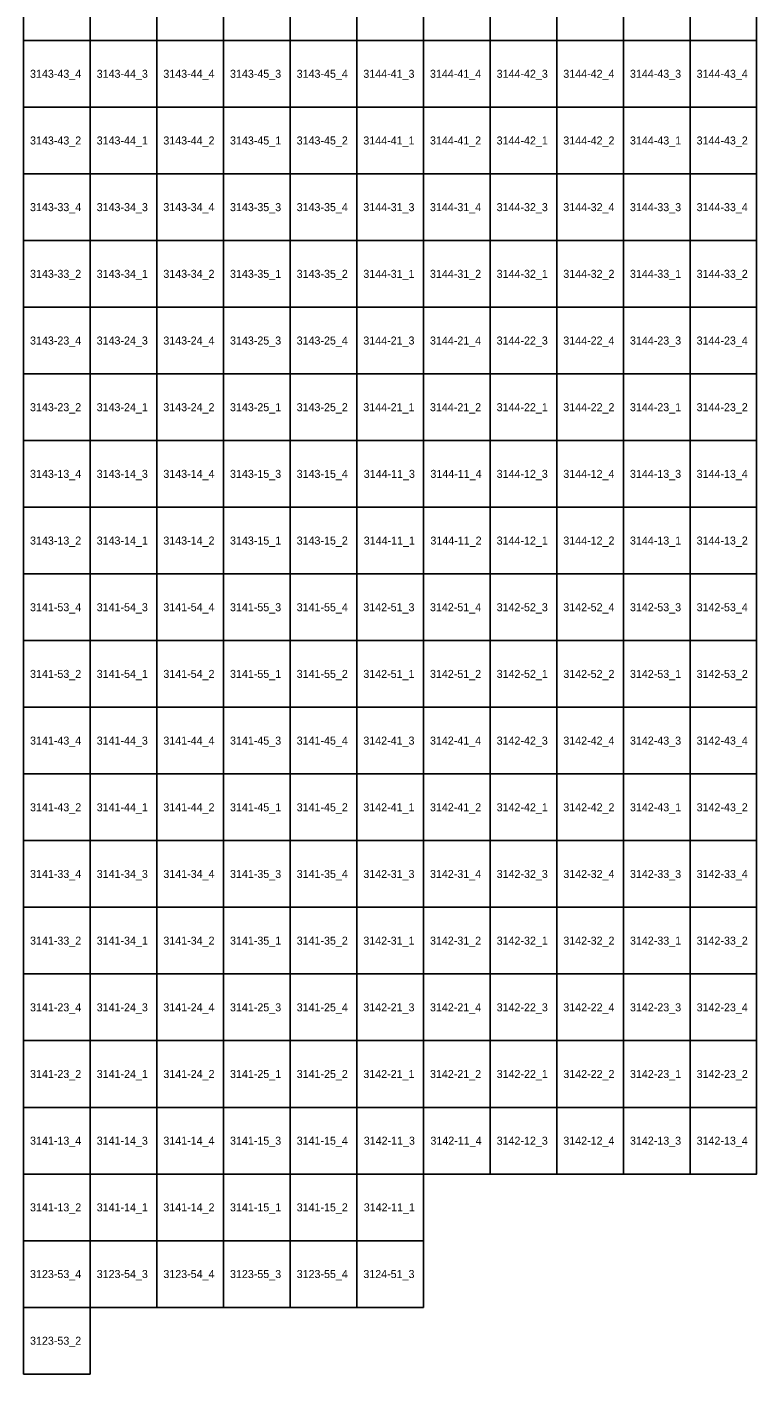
# Model space of a CAD drawing. Extents: x 312500 to 765000, y 172500 to 440000.
# Drawn here: x 362632 to 389827, y 245000 to 295507 of the extents above; entities that cross this region are included whole.
import ezdxf

# ---------------------------------------------------------------- set-up
doc = ezdxf.new("R2010")
doc.units = 0
doc.layers.add('Topo5_ramis_TKS2025', color=7, linetype='Continuous')
doc.layers.add('Topo5_ramis_TKS2025_Nr', color=7, linetype='Continuous')

msp = doc.modelspace()

# ---------------------------------------------------------------- linework, layer by layer
at = {"layer": 'Topo5_ramis_TKS2025'}
for points in [[(362500, 295000), (362500, 297500), (365000, 297500), (365000, 295000), (362500, 295000)], [(365000, 295000), (365000, 297500), (367500, 297500), (367500, 295000), (365000, 295000)], [(367500, 295000), (367500, 297500), (370000, 297500), (370000, 295000), (367500, 295000)], [(370000, 295000), (370000, 297500), (372500, 297500), (372500, 295000), (370000, 295000)], [(372500, 295000), (372500, 297500), (375000, 297500), (375000, 295000), (372500, 295000)], [(375000, 295000), (375000, 297500), (377500, 297500), (377500, 295000), (375000, 295000)], [(377500, 295000), (377500, 297500), (380000, 297500), (380000, 295000), (377500, 295000)], [(380000, 295000), (380000, 297500), (382500, 297500), (382500, 295000), (380000, 295000)], [(382500, 295000), (382500, 297500), (385000, 297500), (385000, 295000), (382500, 295000)], [(385000, 295000), (385000, 297500), (387500, 297500), (387500, 295000), (385000, 295000)], [(387500, 295000), (387500, 297500), (390000, 297500), (390000, 295000), (387500, 295000)], [(362500, 292500), (362500, 295000), (365000, 295000), (365000, 292500), (362500, 292500)], [(365000, 292500), (365000, 295000), (367500, 295000), (367500, 292500), (365000, 292500)], [(367500, 292500), (367500, 295000), (370000, 295000), (370000, 292500), (367500, 292500)], [(370000, 292500), (370000, 295000), (372500, 295000), (372500, 292500), (370000, 292500)], [(372500, 292500), (372500, 295000), (375000, 295000), (375000, 292500), (372500, 292500)], [(375000, 292500), (375000, 295000), (377500, 295000), (377500, 292500), (375000, 292500)], [(377500, 292500), (377500, 295000), (380000, 295000), (380000, 292500), (377500, 292500)], [(380000, 292500), (380000, 295000), (382500, 295000), (382500, 292500), (380000, 292500)], [(382500, 292500), (382500, 295000), (385000, 295000), (385000, 292500), (382500, 292500)], [(385000, 292500), (385000, 295000), (387500, 295000), (387500, 292500), (385000, 292500)], [(387500, 292500), (387500, 295000), (390000, 295000), (390000, 292500), (387500, 292500)], [(362500, 290000), (362500, 292500), (365000, 292500), (365000, 290000), (362500, 290000)], [(365000, 290000), (365000, 292500), (367500, 292500), (367500, 290000), (365000, 290000)], [(367500, 290000), (367500, 292500), (370000, 292500), (370000, 290000), (367500, 290000)], [(370000, 290000), (370000, 292500), (372500, 292500), (372500, 290000), (370000, 290000)], [(372500, 290000), (372500, 292500), (375000, 292500), (375000, 290000), (372500, 290000)], [(375000, 290000), (375000, 292500), (377500, 292500), (377500, 290000), (375000, 290000)], [(377500, 290000), (377500, 292500), (380000, 292500), (380000, 290000), (377500, 290000)], [(380000, 290000), (380000, 292500), (382500, 292500), (382500, 290000), (380000, 290000)], [(382500, 290000), (382500, 292500), (385000, 292500), (385000, 290000), (382500, 290000)], [(385000, 290000), (385000, 292500), (387500, 292500), (387500, 290000), (385000, 290000)], [(387500, 290000), (387500, 292500), (390000, 292500), (390000, 290000), (387500, 290000)], [(362500, 287500), (362500, 290000), (365000, 290000), (365000, 287500), (362500, 287500)], [(365000, 287500), (365000, 290000), (367500, 290000), (367500, 287500), (365000, 287500)], [(367500, 287500), (367500, 290000), (370000, 290000), (370000, 287500), (367500, 287500)], [(370000, 287500), (370000, 290000), (372500, 290000), (372500, 287500), (370000, 287500)], [(372500, 287500), (372500, 290000), (375000, 290000), (375000, 287500), (372500, 287500)], [(375000, 287500), (375000, 290000), (377500, 290000), (377500, 287500), (375000, 287500)], [(377500, 287500), (377500, 290000), (380000, 290000), (380000, 287500), (377500, 287500)], [(380000, 287500), (380000, 290000), (382500, 290000), (382500, 287500), (380000, 287500)], [(382500, 287500), (382500, 290000), (385000, 290000), (385000, 287500), (382500, 287500)], [(385000, 287500), (385000, 290000), (387500, 290000), (387500, 287500), (385000, 287500)], [(387500, 287500), (387500, 290000), (390000, 290000), (390000, 287500), (387500, 287500)], [(362500, 285000), (362500, 287500), (365000, 287500), (365000, 285000), (362500, 285000)], [(365000, 285000), (365000, 287500), (367500, 287500), (367500, 285000), (365000, 285000)], [(367500, 285000), (367500, 287500), (370000, 287500), (370000, 285000), (367500, 285000)], [(370000, 285000), (370000, 287500), (372500, 287500), (372500, 285000), (370000, 285000)], [(372500, 285000), (372500, 287500), (375000, 287500), (375000, 285000), (372500, 285000)], [(375000, 285000), (375000, 287500), (377500, 287500), (377500, 285000), (375000, 285000)], [(377500, 285000), (377500, 287500), (380000, 287500), (380000, 285000), (377500, 285000)], [(380000, 285000), (380000, 287500), (382500, 287500), (382500, 285000), (380000, 285000)], [(382500, 285000), (382500, 287500), (385000, 287500), (385000, 285000), (382500, 285000)], [(385000, 285000), (385000, 287500), (387500, 287500), (387500, 285000), (385000, 285000)], [(387500, 285000), (387500, 287500), (390000, 287500), (390000, 285000), (387500, 285000)], [(362500, 282500), (362500, 285000), (365000, 285000), (365000, 282500), (362500, 282500)], [(365000, 282500), (365000, 285000), (367500, 285000), (367500, 282500), (365000, 282500)], [(367500, 282500), (367500, 285000), (370000, 285000), (370000, 282500), (367500, 282500)], [(370000, 282500), (370000, 285000), (372500, 285000), (372500, 282500), (370000, 282500)], [(372500, 282500), (372500, 285000), (375000, 285000), (375000, 282500), (372500, 282500)], [(375000, 282500), (375000, 285000), (377500, 285000), (377500, 282500), (375000, 282500)], [(377500, 282500), (377500, 285000), (380000, 285000), (380000, 282500), (377500, 282500)], [(380000, 282500), (380000, 285000), (382500, 285000), (382500, 282500), (380000, 282500)], [(382500, 282500), (382500, 285000), (385000, 285000), (385000, 282500), (382500, 282500)], [(385000, 282500), (385000, 285000), (387500, 285000), (387500, 282500), (385000, 282500)], [(387500, 282500), (387500, 285000), (390000, 285000), (390000, 282500), (387500, 282500)], [(362500, 280000), (362500, 282500), (365000, 282500), (365000, 280000), (362500, 280000)], [(365000, 280000), (365000, 282500), (367500, 282500), (367500, 280000), (365000, 280000)], [(367500, 280000), (367500, 282500), (370000, 282500), (370000, 280000), (367500, 280000)], [(370000, 280000), (370000, 282500), (372500, 282500), (372500, 280000), (370000, 280000)], [(372500, 280000), (372500, 282500), (375000, 282500), (375000, 280000), (372500, 280000)], [(375000, 280000), (375000, 282500), (377500, 282500), (377500, 280000), (375000, 280000)], [(377500, 280000), (377500, 282500), (380000, 282500), (380000, 280000), (377500, 280000)], [(380000, 280000), (380000, 282500), (382500, 282500), (382500, 280000), (380000, 280000)], [(382500, 280000), (382500, 282500), (385000, 282500), (385000, 280000), (382500, 280000)], [(385000, 280000), (385000, 282500), (387500, 282500), (387500, 280000), (385000, 280000)], [(387500, 280000), (387500, 282500), (390000, 282500), (390000, 280000), (387500, 280000)], [(362500, 277500), (362500, 280000), (365000, 280000), (365000, 277500), (362500, 277500)], [(365000, 277500), (365000, 280000), (367500, 280000), (367500, 277500), (365000, 277500)], [(367500, 277500), (367500, 280000), (370000, 280000), (370000, 277500), (367500, 277500)], [(370000, 277500), (370000, 280000), (372500, 280000), (372500, 277500), (370000, 277500)], [(372500, 277500), (372500, 280000), (375000, 280000), (375000, 277500), (372500, 277500)], [(375000, 277500), (375000, 280000), (377500, 280000), (377500, 277500), (375000, 277500)], [(377500, 277500), (377500, 280000), (380000, 280000), (380000, 277500), (377500, 277500)], [(380000, 277500), (380000, 280000), (382500, 280000), (382500, 277500), (380000, 277500)], [(382500, 277500), (382500, 280000), (385000, 280000), (385000, 277500), (382500, 277500)], [(385000, 277500), (385000, 280000), (387500, 280000), (387500, 277500), (385000, 277500)], [(387500, 277500), (387500, 280000), (390000, 280000), (390000, 277500), (387500, 277500)], [(362500, 275000), (362500, 277500), (365000, 277500), (365000, 275000), (362500, 275000)], [(365000, 275000), (365000, 277500), (367500, 277500), (367500, 275000), (365000, 275000)], [(367500, 275000), (367500, 277500), (370000, 277500), (370000, 275000), (367500, 275000)], [(370000, 275000), (370000, 277500), (372500, 277500), (372500, 275000), (370000, 275000)], [(372500, 275000), (372500, 277500), (375000, 277500), (375000, 275000), (372500, 275000)], [(375000, 275000), (375000, 277500), (377500, 277500), (377500, 275000), (375000, 275000)], [(377500, 275000), (377500, 277500), (380000, 277500), (380000, 275000), (377500, 275000)], [(380000, 275000), (380000, 277500), (382500, 277500), (382500, 275000), (380000, 275000)], [(382500, 275000), (382500, 277500), (385000, 277500), (385000, 275000), (382500, 275000)], [(385000, 275000), (385000, 277500), (387500, 277500), (387500, 275000), (385000, 275000)], [(387500, 275000), (387500, 277500), (390000, 277500), (390000, 275000), (387500, 275000)], [(362500, 272500), (362500, 275000), (365000, 275000), (365000, 272500), (362500, 272500)], [(365000, 272500), (365000, 275000), (367500, 275000), (367500, 272500), (365000, 272500)], [(367500, 272500), (367500, 275000), (370000, 275000), (370000, 272500), (367500, 272500)], [(370000, 272500), (370000, 275000), (372500, 275000), (372500, 272500), (370000, 272500)], [(372500, 272500), (372500, 275000), (375000, 275000), (375000, 272500), (372500, 272500)], [(375000, 272500), (375000, 275000), (377500, 275000), (377500, 272500), (375000, 272500)], [(377500, 272500), (377500, 275000), (380000, 275000), (380000, 272500), (377500, 272500)], [(380000, 272500), (380000, 275000), (382500, 275000), (382500, 272500), (380000, 272500)], [(382500, 272500), (382500, 275000), (385000, 275000), (385000, 272500), (382500, 272500)], [(385000, 272500), (385000, 275000), (387500, 275000), (387500, 272500), (385000, 272500)], [(387500, 272500), (387500, 275000), (390000, 275000), (390000, 272500), (387500, 272500)], [(362500, 270000), (362500, 272500), (365000, 272500), (365000, 270000), (362500, 270000)], [(365000, 270000), (365000, 272500), (367500, 272500), (367500, 270000), (365000, 270000)], [(367500, 270000), (367500, 272500), (370000, 272500), (370000, 270000), (367500, 270000)], [(370000, 270000), (370000, 272500), (372500, 272500), (372500, 270000), (370000, 270000)], [(372500, 270000), (372500, 272500), (375000, 272500), (375000, 270000), (372500, 270000)], [(375000, 270000), (375000, 272500), (377500, 272500), (377500, 270000), (375000, 270000)], [(377500, 270000), (377500, 272500), (380000, 272500), (380000, 270000), (377500, 270000)], [(380000, 270000), (380000, 272500), (382500, 272500), (382500, 270000), (380000, 270000)], [(382500, 270000), (382500, 272500), (385000, 272500), (385000, 270000), (382500, 270000)], [(385000, 270000), (385000, 272500), (387500, 272500), (387500, 270000), (385000, 270000)], [(387500, 270000), (387500, 272500), (390000, 272500), (390000, 270000), (387500, 270000)], [(362500, 267500), (362500, 270000), (365000, 270000), (365000, 267500), (362500, 267500)], [(365000, 267500), (365000, 270000), (367500, 270000), (367500, 267500), (365000, 267500)], [(367500, 267500), (367500, 270000), (370000, 270000), (370000, 267500), (367500, 267500)], [(370000, 267500), (370000, 270000), (372500, 270000), (372500, 267500), (370000, 267500)], [(372500, 267500), (372500, 270000), (375000, 270000), (375000, 267500), (372500, 267500)], [(375000, 267500), (375000, 270000), (377500, 270000), (377500, 267500), (375000, 267500)], [(377500, 267500), (377500, 270000), (380000, 270000), (380000, 267500), (377500, 267500)], [(380000, 267500), (380000, 270000), (382500, 270000), (382500, 267500), (380000, 267500)], [(382500, 267500), (382500, 270000), (385000, 270000), (385000, 267500), (382500, 267500)], [(385000, 267500), (385000, 270000), (387500, 270000), (387500, 267500), (385000, 267500)], [(387500, 267500), (387500, 270000), (390000, 270000), (390000, 267500), (387500, 267500)], [(362500, 265000), (362500, 267500), (365000, 267500), (365000, 265000), (362500, 265000)], [(365000, 265000), (365000, 267500), (367500, 267500), (367500, 265000), (365000, 265000)], [(367500, 265000), (367500, 267500), (370000, 267500), (370000, 265000), (367500, 265000)], [(370000, 265000), (370000, 267500), (372500, 267500), (372500, 265000), (370000, 265000)], [(372500, 265000), (372500, 267500), (375000, 267500), (375000, 265000), (372500, 265000)], [(375000, 265000), (375000, 267500), (377500, 267500), (377500, 265000), (375000, 265000)], [(377500, 265000), (377500, 267500), (380000, 267500), (380000, 265000), (377500, 265000)], [(380000, 265000), (380000, 267500), (382500, 267500), (382500, 265000), (380000, 265000)], [(382500, 265000), (382500, 267500), (385000, 267500), (385000, 265000), (382500, 265000)], [(385000, 265000), (385000, 267500), (387500, 267500), (387500, 265000), (385000, 265000)], [(387500, 265000), (387500, 267500), (390000, 267500), (390000, 265000), (387500, 265000)], [(362500, 262500), (362500, 265000), (365000, 265000), (365000, 262500), (362500, 262500)], [(365000, 262500), (365000, 265000), (367500, 265000), (367500, 262500), (365000, 262500)], [(367500, 262500), (367500, 265000), (370000, 265000), (370000, 262500), (367500, 262500)], [(370000, 262500), (370000, 265000), (372500, 265000), (372500, 262500), (370000, 262500)], [(372500, 262500), (372500, 265000), (375000, 265000), (375000, 262500), (372500, 262500)], [(375000, 262500), (375000, 265000), (377500, 265000), (377500, 262500), (375000, 262500)], [(377500, 262500), (377500, 265000), (380000, 265000), (380000, 262500), (377500, 262500)], [(380000, 262500), (380000, 265000), (382500, 265000), (382500, 262500), (380000, 262500)], [(382500, 262500), (382500, 265000), (385000, 265000), (385000, 262500), (382500, 262500)], [(385000, 262500), (385000, 265000), (387500, 265000), (387500, 262500), (385000, 262500)], [(387500, 262500), (387500, 265000), (390000, 265000), (390000, 262500), (387500, 262500)], [(362500, 260000), (362500, 262500), (365000, 262500), (365000, 260000), (362500, 260000)], [(365000, 260000), (365000, 262500), (367500, 262500), (367500, 260000), (365000, 260000)], [(367500, 260000), (367500, 262500), (370000, 262500), (370000, 260000), (367500, 260000)], [(370000, 260000), (370000, 262500), (372500, 262500), (372500, 260000), (370000, 260000)], [(372500, 260000), (372500, 262500), (375000, 262500), (375000, 260000), (372500, 260000)], [(375000, 260000), (375000, 262500), (377500, 262500), (377500, 260000), (375000, 260000)], [(377500, 260000), (377500, 262500), (380000, 262500), (380000, 260000), (377500, 260000)], [(380000, 260000), (380000, 262500), (382500, 262500), (382500, 260000), (380000, 260000)], [(382500, 260000), (382500, 262500), (385000, 262500), (385000, 260000), (382500, 260000)], [(385000, 260000), (385000, 262500), (387500, 262500), (387500, 260000), (385000, 260000)], [(387500, 260000), (387500, 262500), (390000, 262500), (390000, 260000), (387500, 260000)], [(362500, 257500), (362500, 260000), (365000, 260000), (365000, 257500), (362500, 257500)], [(365000, 257500), (365000, 260000), (367500, 260000), (367500, 257500), (365000, 257500)], [(367500, 257500), (367500, 260000), (370000, 260000), (370000, 257500), (367500, 257500)], [(370000, 257500), (370000, 260000), (372500, 260000), (372500, 257500), (370000, 257500)], [(372500, 257500), (372500, 260000), (375000, 260000), (375000, 257500), (372500, 257500)], [(375000, 257500), (375000, 260000), (377500, 260000), (377500, 257500), (375000, 257500)], [(377500, 257500), (377500, 260000), (380000, 260000), (380000, 257500), (377500, 257500)], [(380000, 257500), (380000, 260000), (382500, 260000), (382500, 257500), (380000, 257500)], [(382500, 257500), (382500, 260000), (385000, 260000), (385000, 257500), (382500, 257500)], [(385000, 257500), (385000, 260000), (387500, 260000), (387500, 257500), (385000, 257500)], [(387500, 257500), (387500, 260000), (390000, 260000), (390000, 257500), (387500, 257500)], [(362500, 255000), (362500, 257500), (365000, 257500), (365000, 255000), (362500, 255000)], [(365000, 255000), (365000, 257500), (367500, 257500), (367500, 255000), (365000, 255000)], [(367500, 255000), (367500, 257500), (370000, 257500), (370000, 255000), (367500, 255000)], [(370000, 255000), (370000, 257500), (372500, 257500), (372500, 255000), (370000, 255000)], [(372500, 255000), (372500, 257500), (375000, 257500), (375000, 255000), (372500, 255000)], [(375000, 255000), (375000, 257500), (377500, 257500), (377500, 255000), (375000, 255000)], [(377500, 255000), (377500, 257500), (380000, 257500), (380000, 255000), (377500, 255000)], [(380000, 255000), (380000, 257500), (382500, 257500), (382500, 255000), (380000, 255000)], [(382500, 255000), (382500, 257500), (385000, 257500), (385000, 255000), (382500, 255000)], [(385000, 255000), (385000, 257500), (387500, 257500), (387500, 255000), (385000, 255000)], [(387500, 255000), (387500, 257500), (390000, 257500), (390000, 255000), (387500, 255000)], [(362500, 252500), (362500, 255000), (365000, 255000), (365000, 252500), (362500, 252500)], [(365000, 252500), (365000, 255000), (367500, 255000), (367500, 252500), (365000, 252500)], [(367500, 252500), (367500, 255000), (370000, 255000), (370000, 252500), (367500, 252500)], [(370000, 252500), (370000, 255000), (372500, 255000), (372500, 252500), (370000, 252500)], [(372500, 252500), (372500, 255000), (375000, 255000), (375000, 252500), (372500, 252500)], [(375000, 252500), (375000, 255000), (377500, 255000), (377500, 252500), (375000, 252500)], [(377500, 252500), (377500, 255000), (380000, 255000), (380000, 252500), (377500, 252500)], [(380000, 252500), (380000, 255000), (382500, 255000), (382500, 252500), (380000, 252500)], [(382500, 252500), (382500, 255000), (385000, 255000), (385000, 252500), (382500, 252500)], [(385000, 252500), (385000, 255000), (387500, 255000), (387500, 252500), (385000, 252500)], [(387500, 252500), (387500, 255000), (390000, 255000), (390000, 252500), (387500, 252500)], [(362500, 250000), (362500, 252500), (365000, 252500), (365000, 250000), (362500, 250000)], [(365000, 250000), (365000, 252500), (367500, 252500), (367500, 250000), (365000, 250000)], [(367500, 250000), (367500, 252500), (370000, 252500), (370000, 250000), (367500, 250000)], [(370000, 250000), (370000, 252500), (372500, 252500), (372500, 250000), (370000, 250000)], [(372500, 250000), (372500, 252500), (375000, 252500), (375000, 250000), (372500, 250000)], [(375000, 250000), (375000, 252500), (377500, 252500), (377500, 250000), (375000, 250000)], [(362500, 247500), (362500, 250000), (365000, 250000), (365000, 247500), (362500, 247500)], [(365000, 247500), (365000, 250000), (367500, 250000), (367500, 247500), (365000, 247500)], [(367500, 247500), (367500, 250000), (370000, 250000), (370000, 247500), (367500, 247500)], [(370000, 247500), (370000, 250000), (372500, 250000), (372500, 247500), (370000, 247500)], [(372500, 247500), (372500, 250000), (375000, 250000), (375000, 247500), (372500, 247500)], [(375000, 247500), (375000, 250000), (377500, 250000), (377500, 247500), (375000, 247500)], [(362500, 245000), (362500, 247500), (365000, 247500), (365000, 245000), (362500, 245000)]]:
    msp.add_lwpolyline(points, dxfattribs=at)

# ---------------------------------------------------------------- texts
at = {"layer": 'Topo5_ramis_TKS2025_Nr'}
for s, p in [('3143-43_4', (362748, 293600)), ('3143-44_3', (365248, 293600)), ('3143-44_4', (367748, 293600)), ('3143-45_3', (370248, 293600)), ('3143-45_4', (372748, 293600)), ('3144-41_3', (375248, 293600)), ('3144-41_4', (377748, 293600)), ('3144-42_3', (380248, 293600)), ('3144-42_4', (382748, 293600)), ('3144-43_3', (385248, 293600)), ('3144-43_4', (387748, 293600)), ('3143-43_2', (362748, 291100)), ('3143-44_1', (365248, 291100)), ('3143-44_2', (367748, 291100)), ('3143-45_1', (370248, 291100)), ('3143-45_2', (372748, 291100)), ('3144-41_1', (375248, 291100)), ('3144-41_2', (377748, 291100)), ('3144-42_1', (380248, 291100)), ('3144-42_2', (382748, 291100)), ('3144-43_1', (385248, 291100)), ('3144-43_2', (387748, 291100)), ('3143-33_4', (362748, 288600)), ('3143-34_3', (365248, 288600)), ('3143-34_4', (367748, 288600)), ('3143-35_3', (370248, 288600)), ('3143-35_4', (372748, 288600)), ('3144-31_3', (375248, 288600)), ('3144-31_4', (377748, 288600)), ('3144-32_3', (380248, 288600)), ('3144-32_4', (382748, 288600)), ('3144-33_3', (385248, 288600)), ('3144-33_4', (387748, 288600)), ('3143-33_2', (362748, 286100)), ('3143-34_1', (365248, 286100)), ('3143-34_2', (367748, 286100)), ('3143-35_1', (370248, 286100)), ('3143-35_2', (372748, 286100)), ('3144-31_1', (375248, 286100)), ('3144-31_2', (377748, 286100)), ('3144-32_1', (380248, 286100)), ('3144-32_2', (382748, 286100)), ('3144-33_1', (385248, 286100)), ('3144-33_2', (387748, 286100)), ('3143-23_4', (362748, 283600)), ('3143-24_3', (365248, 283600)), ('3143-24_4', (367748, 283600)), ('3143-25_3', (370248, 283600)), ('3143-25_4', (372748, 283600)), ('3144-21_3', (375248, 283600)), ('3144-21_4', (377748, 283600)), ('3144-22_3', (380248, 283600)), ('3144-22_4', (382748, 283600)), ('3144-23_3', (385248, 283600)), ('3144-23_4', (387748, 283600)), ('3143-23_2', (362748, 281100)), ('3143-24_1', (365248, 281100)), ('3143-24_2', (367748, 281100)), ('3143-25_1', (370248, 281100)), ('3143-25_2', (372748, 281100)), ('3144-21_1', (375248, 281100)), ('3144-21_2', (377748, 281100)), ('3144-22_1', (380248, 281100)), ('3144-22_2', (382748, 281100)), ('3144-23_1', (385248, 281100)), ('3144-23_2', (387748, 281100)), ('3143-13_4', (362748, 278600)), ('3143-14_3', (365248, 278600)), ('3143-14_4', (367748, 278600)), ('3143-15_3', (370248, 278600)), ('3143-15_4', (372748, 278600)), ('3144-11_3', (375264, 278600)), ('3144-11_4', (377764, 278600)), ('3144-12_3', (380248, 278600)), ('3144-12_4', (382748, 278600)), ('3144-13_3', (385248, 278600)), ('3144-13_4', (387748, 278600)), ('3143-13_2', (362748, 276100)), ('3143-14_1', (365248, 276100)), ('3143-14_2', (367748, 276100)), ('3143-15_1', (370248, 276100)), ('3143-15_2', (372748, 276100)), ('3144-11_1', (375264, 276100)), ('3144-11_2', (377764, 276100)), ('3144-12_1', (380248, 276100)), ('3144-12_2', (382748, 276100)), ('3144-13_1', (385248, 276100)), ('3144-13_2', (387748, 276100)), ('3141-53_4', (362748, 273600)), ('3141-54_3', (365248, 273600)), ('3141-54_4', (367748, 273600)), ('3141-55_3', (370248, 273600)), ('3141-55_4', (372748, 273600)), ('3142-51_3', (375248, 273600)), ('3142-51_4', (377748, 273600)), ('3142-52_3', (380248, 273600)), ('3142-52_4', (382748, 273600)), ('3142-53_3', (385248, 273600)), ('3142-53_4', (387748, 273600)), ('3141-53_2', (362748, 271100)), ('3141-54_1', (365248, 271100)), ('3141-54_2', (367748, 271100)), ('3141-55_1', (370248, 271100)), ('3141-55_2', (372748, 271100)), ('3142-51_1', (375248, 271100)), ('3142-51_2', (377748, 271100)), ('3142-52_1', (380248, 271100)), ('3142-52_2', (382748, 271100)), ('3142-53_1', (385248, 271100)), ('3142-53_2', (387748, 271100)), ('3141-43_4', (362748, 268600)), ('3141-44_3', (365248, 268600)), ('3141-44_4', (367748, 268600)), ('3141-45_3', (370248, 268600)), ('3141-45_4', (372748, 268600)), ('3142-41_3', (375248, 268600)), ('3142-41_4', (377748, 268600)), ('3142-42_3', (380248, 268600)), ('3142-42_4', (382748, 268600)), ('3142-43_3', (385248, 268600)), ('3142-43_4', (387748, 268600)), ('3141-43_2', (362748, 266100)), ('3141-44_1', (365248, 266100)), ('3141-44_2', (367748, 266100)), ('3141-45_1', (370248, 266100)), ('3141-45_2', (372748, 266100)), ('3142-41_1', (375248, 266100)), ('3142-41_2', (377748, 266100)), ('3142-42_1', (380248, 266100)), ('3142-42_2', (382748, 266100)), ('3142-43_1', (385248, 266100)), ('3142-43_2', (387748, 266100)), ('3141-33_4', (362748, 263600)), ('3141-34_3', (365248, 263600)), ('3141-34_4', (367748, 263600)), ('3141-35_3', (370248, 263600)), ('3141-35_4', (372748, 263600)), ('3142-31_3', (375248, 263600)), ('3142-31_4', (377748, 263600)), ('3142-32_3', (380248, 263600)), ('3142-32_4', (382748, 263600)), ('3142-33_3', (385248, 263600)), ('3142-33_4', (387748, 263600)), ('3141-33_2', (362748, 261100)), ('3141-34_1', (365248, 261100)), ('3141-34_2', (367748, 261100)), ('3141-35_1', (370248, 261100)), ('3141-35_2', (372748, 261100)), ('3142-31_1', (375248, 261100)), ('3142-31_2', (377748, 261100)), ('3142-32_1', (380248, 261100)), ('3142-32_2', (382748, 261100)), ('3142-33_1', (385248, 261100)), ('3142-33_2', (387748, 261100)), ('3141-23_4', (362748, 258600)), ('3141-24_3', (365248, 258600)), ('3141-24_4', (367748, 258600)), ('3141-25_3', (370248, 258600)), ('3141-25_4', (372748, 258600)), ('3142-21_3', (375248, 258600)), ('3142-21_4', (377748, 258600)), ('3142-22_3', (380248, 258600)), ('3142-22_4', (382748, 258600)), ('3142-23_3', (385248, 258600)), ('3142-23_4', (387748, 258600)), ('3141-23_2', (362748, 256100)), ('3141-24_1', (365248, 256100)), ('3141-24_2', (367748, 256100)), ('3141-25_1', (370248, 256100)), ('3141-25_2', (372748, 256100)), ('3142-21_1', (375248, 256100)), ('3142-21_2', (377748, 256100)), ('3142-22_1', (380248, 256100)), ('3142-22_2', (382748, 256100)), ('3142-23_1', (385248, 256100)), ('3142-23_2', (387748, 256100)), ('3141-13_4', (362748, 253600)), ('3141-14_3', (365248, 253600)), ('3141-14_4', (367748, 253600)), ('3141-15_3', (370248, 253600)), ('3141-15_4', (372748, 253600)), ('3142-11_3', (375264, 253600)), ('3142-11_4', (377764, 253600)), ('3142-12_3', (380248, 253600)), ('3142-12_4', (382748, 253600)), ('3142-13_3', (385248, 253600)), ('3142-13_4', (387748, 253600)), ('3141-13_2', (362748, 251100)), ('3141-14_1', (365248, 251100)), ('3141-14_2', (367748, 251100)), ('3141-15_1', (370248, 251100)), ('3141-15_2', (372748, 251100)), ('3142-11_1', (375264, 251100)), ('3123-53_4', (362748, 248600)), ('3123-54_3', (365248, 248600)), ('3123-54_4', (367748, 248600)), ('3123-55_3', (370248, 248600)), ('3123-55_4', (372748, 248600)), ('3124-51_3', (375248, 248600)), ('3123-53_2', (362748, 246100))]:
    msp.add_text(s, height=300, dxfattribs=at).set_placement(p)

doc.saveas('drawing.dxf')
